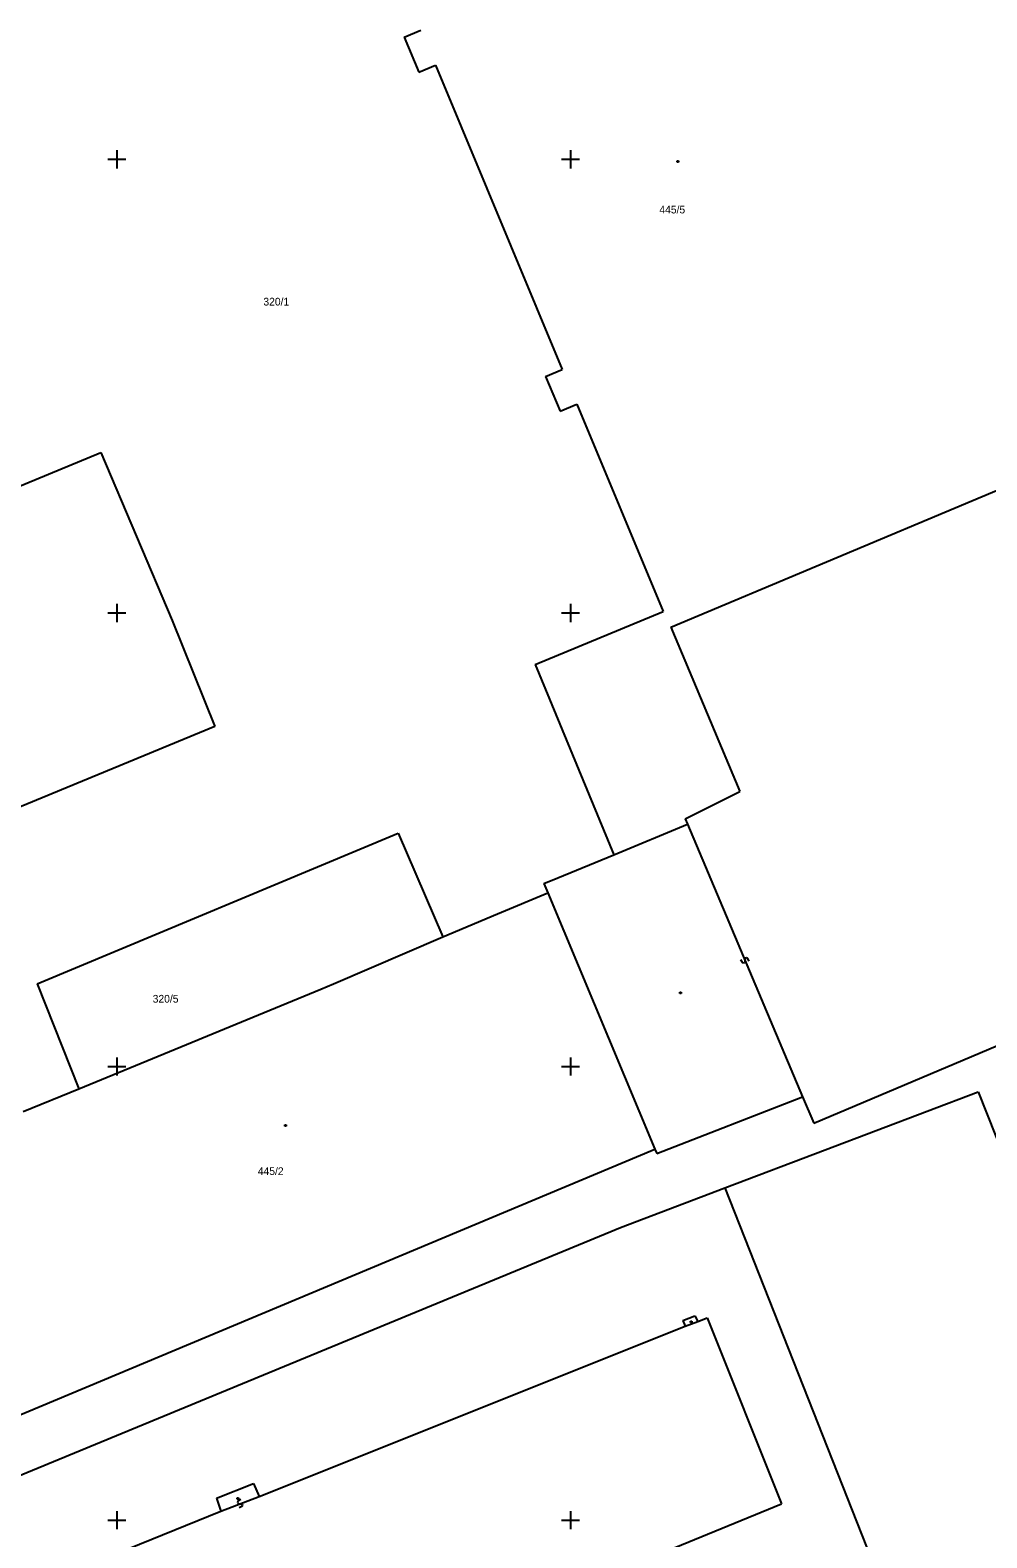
# Model space of a CAD drawing. Extents: x -492379 to -491966, y -1126153 to -1125860.
# Drawn here: x -492095.7 to -492032.5, y -1125961.2 to -1125861.5 of the extents above; entities that cross this region are included whole.
import ezdxf

# ---------------------------------------------------------------- set-up
doc = ezdxf.new("R2010")
doc.units = 0
doc.layers.add('katastrální mapa', color=7, linetype='Continuous')
doc.layers.add('síť', color=7, linetype='Continuous')

msp = doc.modelspace()

# ---------------------------------------------------------------- linework, layer by layer
at = {"layer": 'katastrální mapa'}
for p, q in [((-492071, -1125861.92), (-492069.89, -1125861.46)), ((-492071, -1125861.92), (-492070.04, -1125864.23)), ((-492070.04, -1125864.23), (-492068.93, -1125863.77)), ((-492068.93, -1125863.77), (-492060.55, -1125883.9)), ((-492052.95, -1125870.11), (-492052.86, -1125870.11)), ((-492052.95, -1125870.2), (-492052.95, -1125870.11)), ((-492052.86, -1125870.2), (-492052.95, -1125870.2)), ((-492052.86, -1125870.11), (-492052.86, -1125870.2)), ((-492032.79, -1125892.29), (-492012.18, -1125883.64)), ((-492061.66, -1125884.36), (-492060.55, -1125883.9)), ((-492061.66, -1125884.36), (-492060.7, -1125886.66)), ((-492060.7, -1125886.66), (-492059.59, -1125886.2)), ((-492059.59, -1125886.2), (-492053.88, -1125899.91)), ((-492150.75, -1125914.23), (-492091.06, -1125889.38)), ((-492091.06, -1125889.38), (-492086.35, -1125900.5)), ((-492053.38, -1125900.94), (-492032.79, -1125892.29)), ((-492086.35, -1125900.5), (-492083.52, -1125907.5)), ((-492062.35, -1125903.42), (-492053.88, -1125899.91)), ((-492053.38, -1125900.94), (-492048.82, -1125911.81)), ((-492062.35, -1125903.42), (-492057.15, -1125915.99)), ((-492083.52, -1125907.5), (-492118.89, -1125922.15)), ((-492052.43, -1125913.61), (-492048.82, -1125911.81)), ((-492052.43, -1125913.61), (-492052.28, -1125913.97)), ((-492095.26, -1125924.53), (-492071.41, -1125914.56)), ((-492071.41, -1125914.56), (-492068.45, -1125921.42)), ((-492057.15, -1125915.99), (-492052.28, -1125913.97)), ((-492052.28, -1125913.97), (-492044.66, -1125931.99)), ((-492043.92, -1125933.74), (-491999.27, -1125914.83)), ((-492060.84, -1125917.52), (-492057.15, -1125915.99)), ((-492061.76, -1125917.9), (-492060.84, -1125917.52)), ((-492064.84, -1125919.9), (-492061.51, -1125918.5)), ((-492061.76, -1125917.9), (-492061.51, -1125918.5)), ((-492061.51, -1125918.5), (-492054.42, -1125935.46)), ((-492068.45, -1125921.42), (-492064.84, -1125919.9)), ((-492075.68, -1125924.52), (-492068.45, -1125921.42)), ((-492048.64, -1125923.12), (-492048.75, -1125922.94)), ((-492048.56, -1125923.15), (-492048.64, -1125923.12)), ((-492048.51, -1125923.13), (-492048.56, -1125923.15)), ((-492048.47, -1125923.05), (-492048.51, -1125923.13)), ((-492048.43, -1125922.83), (-492048.47, -1125922.91)), ((-492048.47, -1125922.91), (-492048.47, -1125923.05)), ((-492048.38, -1125922.81), (-492048.43, -1125922.83)), ((-492048.3, -1125922.84), (-492048.38, -1125922.81)), ((-492048.19, -1125923.02), (-492048.3, -1125922.84)), ((-492095.26, -1125924.53), (-492092.51, -1125931.47)), ((-492076.52, -1125924.87), (-492075.68, -1125924.52)), ((-492092.51, -1125931.47), (-492076.52, -1125924.87)), ((-492052.78, -1125925.07), (-492052.69, -1125925.07)), ((-492052.78, -1125925.16), (-492052.78, -1125925.07)), ((-492052.69, -1125925.16), (-492052.78, -1125925.16)), ((-492052.69, -1125925.07), (-492052.69, -1125925.16)), ((-492096.2, -1125932.98), (-492092.51, -1125931.47)), ((-492043.17, -1125935.5), (-492033.05, -1125931.66)), ((-492033.05, -1125931.66), (-492007.69, -1125995.9)), ((-492054.3, -1125935.74), (-492044.66, -1125931.99)), ((-492044.66, -1125931.99), (-492043.92, -1125933.74)), ((-492078.89, -1125933.86), (-492078.8, -1125933.86)), ((-492078.89, -1125933.95), (-492078.89, -1125933.86)), ((-492078.8, -1125933.95), (-492078.89, -1125933.95)), ((-492078.8, -1125933.86), (-492078.8, -1125933.95)), ((-492098.58, -1125953.94), (-492054.42, -1125935.46)), ((-492054.42, -1125935.46), (-492054.3, -1125935.74)), ((-492049.8, -1125938.02), (-492043.17, -1125935.5)), ((-492056.7, -1125940.64), (-492049.8, -1125938.02)), ((-492049.8, -1125938.02), (-492020.7, -1126011.81)), ((-492119.27, -1125966.48), (-492056.7, -1125940.64)), ((-492052.58, -1125946.79), (-492051.78, -1125946.49)), ((-492051.78, -1125946.49), (-492051.58, -1125946.85)), ((-492051.58, -1125946.85), (-492050.98, -1125946.61)), ((-492050.98, -1125946.61), (-492046.06, -1125958.91)), ((-492080.6, -1125958.42), (-492052.42, -1125947.17)), ((-492052.58, -1125946.79), (-492052.42, -1125947.17)), ((-492052.42, -1125947.17), (-492051.58, -1125946.85)), ((-492052.08, -1125946.84), (-492051.99, -1125946.84)), ((-492052.08, -1125946.93), (-492052.08, -1125946.84)), ((-492051.99, -1125946.93), (-492052.08, -1125946.93)), ((-492051.99, -1125946.84), (-492051.99, -1125946.93)), ((-492083.4, -1125958.53), (-492080.96, -1125957.57)), ((-492080.96, -1125957.57), (-492080.6, -1125958.42)), ((-492083.4, -1125958.53), (-492083.13, -1125959.41)), ((-492083.13, -1125959.41), (-492080.6, -1125958.42)), ((-492082.04, -1125958.51), (-492081.95, -1125958.51)), ((-492082.04, -1125958.6), (-492082.04, -1125958.51)), ((-492081.95, -1125958.51), (-492081.95, -1125958.6)), ((-492094.1, -1125963.84), (-492083.13, -1125959.41)), ((-492081.95, -1125958.6), (-492082.04, -1125958.6)), ((-492082, -1125958.74), (-492082.03, -1125958.82)), ((-492082.03, -1125958.82), (-492082.01, -1125958.87)), ((-492082.01, -1125958.87), (-492081.93, -1125958.91)), ((-492081.81, -1125958.64), (-492082, -1125958.74)), ((-492081.93, -1125958.91), (-492081.8, -1125958.92)), ((-492081.73, -1125959.09), (-492081.92, -1125959.19)), ((-492081.8, -1125958.92), (-492081.72, -1125958.96)), ((-492081.7, -1125959.01), (-492081.73, -1125959.09)), ((-492081.72, -1125958.96), (-492081.7, -1125959.01)), ((-492074.82, -1125970.7), (-492046.06, -1125958.91))]:
    msp.add_line(p, q, dxfattribs=at)
at = {"layer": 'síť'}
for p, q in [((-492090, -1125869.4), (-492090, -1125870.6)), ((-492060, -1125869.4), (-492060, -1125870.6)), ((-492090.6, -1125870), (-492089.4, -1125870)), ((-492060.6, -1125870), (-492059.4, -1125870)), ((-492090, -1125899.4), (-492090, -1125900.6)), ((-492060, -1125899.4), (-492060, -1125900.6)), ((-492090.6, -1125900), (-492089.4, -1125900)), ((-492060.6, -1125900), (-492059.4, -1125900)), ((-492090, -1125929.4), (-492090, -1125930.6)), ((-492060, -1125929.4), (-492060, -1125930.6)), ((-492090.6, -1125930), (-492089.4, -1125930)), ((-492060.6, -1125930), (-492059.4, -1125930)), ((-492090, -1125959.4), (-492090, -1125960.6)), ((-492060, -1125959.4), (-492060, -1125960.6)), ((-492090.6, -1125960), (-492089.4, -1125960)), ((-492060.6, -1125960), (-492059.4, -1125960))]:
    msp.add_line(p, q, dxfattribs=at)

# ---------------------------------------------------------------- texts
at = {"layer": 'katastrální mapa'}
for s, p in [('445/5', (-492054.13, -1125873.58)), ('320/1', (-492080.31, -1125879.67)), ('320/5', (-492087.63, -1125925.77)), ('445/2', (-492080.68, -1125937.17))]:
    msp.add_text(s, height=0.51, dxfattribs=at).set_placement(p)

doc.saveas('drawing.dxf')
